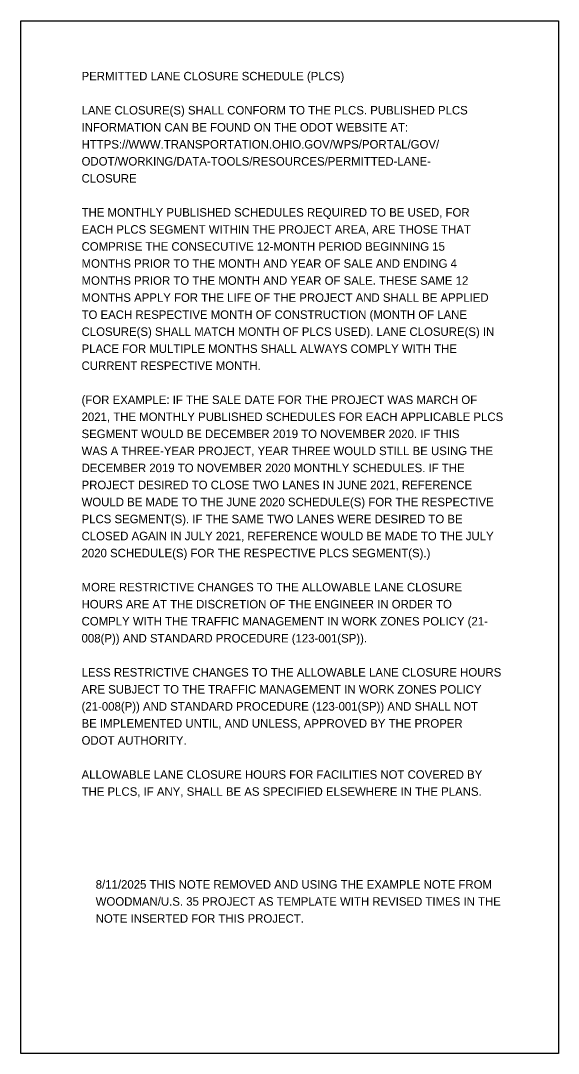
# Model space of a CAD drawing. Extents: x -25.5 to 52.6, y -2.3 to 22.
# Drawn here: x 43.74 to 52.58, y -2.27 to 14.7 of the extents above; entities that cross this region are included whole.
import ezdxf

# ---------------------------------------------------------------- set-up
doc = ezdxf.new("R2010")
doc.units = 0
doc.layers.add('SH_Text', color=7, linetype='Continuous')

msp = doc.modelspace()

# ---------------------------------------------------------------- linework, layer by layer
at = {"layer": 'SH_Text'}
msp.add_lwpolyline([(43.74, 14.702), (52.576, 14.702), (52.576, -2.274), (43.74, -2.274)], close=True, dxfattribs=at)

# ---------------------------------------------------------------- texts
for s, p in [('PERMITTED LANE CLOSURE SCHEDULE (PLCS)', (44.741, 13.72)), ('LANE CLOSURE(S) SHALL CONFORM TO THE PLCS. PUBLISHED PLCS ', (44.741, 13.16)), ('INFORMATION CAN BE FOUND ON THE ODOT WEBSITE AT: ', (44.741, 12.88)), ('HTTPS://WWW.TRANSPORTATION.OHIO.GOV/WPS/PORTAL/GOV/', (44.741, 12.6)), ('ODOT/WORKING/DATA-TOOLS/RESOURCES/PERMITTED-LANE-', (44.741, 12.32)), ('CLOSURE', (44.741, 12.04)), ('THE MONTHLY PUBLISHED SCHEDULES REQUIRED TO BE USED, FOR ', (44.741, 11.48)), ('EACH PLCS SEGMENT WITHIN THE PROJECT AREA, ARE THOSE THAT ', (44.741, 11.2)), ('COMPRISE THE CONSECUTIVE 12-MONTH PERIOD BEGINNING 15 ', (44.741, 10.92)), ('MONTHS PRIOR TO THE MONTH AND YEAR OF SALE AND ENDING 4 ', (44.741, 10.64)), ('MONTHS PRIOR TO THE MONTH AND YEAR OF SALE. THESE SAME 12 ', (44.741, 10.36)), ('MONTHS APPLY FOR THE LIFE OF THE PROJECT AND SHALL BE APPLIED ', (44.741, 10.08)), ('TO EACH RESPECTIVE MONTH OF CONSTRUCTION (MONTH OF LANE ', (44.741, 9.8)), ('CLOSURE(S) SHALL MATCH MONTH OF PLCS USED). LANE CLOSURE(S) IN ', (44.741, 9.52)), ('PLACE FOR MULTIPLE MONTHS SHALL ALWAYS COMPLY WITH THE ', (44.741, 9.24)), ('CURRENT RESPECTIVE MONTH. ', (44.741, 8.96)), ('(FOR EXAMPLE: IF THE SALE DATE FOR THE PROJECT WAS MARCH OF ', (44.741, 8.4)), ('2021, THE MONTHLY PUBLISHED SCHEDULES FOR EACH APPLICABLE PLCS ', (44.741, 8.12)), ('SEGMENT WOULD BE DECEMBER 2019 TO NOVEMBER 2020. IF THIS ', (44.741, 7.84)), ('WAS A THREE-YEAR PROJECT, YEAR THREE WOULD STILL BE USING THE ', (44.741, 7.56)), ('DECEMBER 2019 TO NOVEMBER 2020 MONTHLY SCHEDULES. IF THE ', (44.741, 7.28)), ('PROJECT DESIRED TO CLOSE TWO LANES IN JUNE 2021, REFERENCE ', (44.741, 7)), ('WOULD BE MADE TO THE JUNE 2020 SCHEDULE(S) FOR THE RESPECTIVE ', (44.741, 6.72)), ('PLCS SEGMENT(S). IF THE SAME TWO LANES WERE DESIRED TO BE ', (44.741, 6.44)), ('CLOSED AGAIN IN JULY 2021, REFERENCE WOULD BE MADE TO THE JULY ', (44.741, 6.16)), ('2020 SCHEDULE(S) FOR THE RESPECTIVE PLCS SEGMENT(S).)', (44.741, 5.88)), ('MORE RESTRICTIVE CHANGES TO THE ALLOWABLE LANE CLOSURE ', (44.741, 5.32)), ('HOURS ARE AT THE DISCRETION OF THE ENGINEER IN ORDER TO ', (44.741, 5.04)), ('COMPLY WITH THE TRAFFIC MANAGEMENT IN WORK ZONES POLICY (21-', (44.741, 4.76)), ('008(P)) AND STANDARD PROCEDURE (123-001(SP)). ', (44.741, 4.48)), ('LESS RESTRICTIVE CHANGES TO THE ALLOWABLE LANE CLOSURE HOURS ', (44.741, 3.92)), ('ARE SUBJECT TO THE TRAFFIC MANAGEMENT IN WORK ZONES POLICY ', (44.741, 3.64)), ('(21-008(P)) AND STANDARD PROCEDURE (123-001(SP)) AND SHALL NOT ', (44.741, 3.36)), ('BE IMPLEMENTED UNTIL, AND UNLESS, APPROVED BY THE PROPER ', (44.741, 3.08)), ('ODOT AUTHORITY.', (44.741, 2.8)), ('ALLOWABLE LANE CLOSURE HOURS FOR FACILITIES NOT COVERED BY ', (44.741, 2.24)), ('THE PLCS, IF ANY, SHALL BE AS SPECIFIED ELSEWHERE IN THE PLANS.', (44.741, 1.96)), ('8/11/2025 THIS NOTE REMOVED AND USING THE EXAMPLE NOTE FROM ', (44.973, 0.433)), ('WOODMAN/U.S. 35 PROJECT AS TEMPLATE WITH REVISED TIMES IN THE ', (44.973, 0.153)), ('NOTE INSERTED FOR THIS PROJECT.', (44.973, -0.127))]:
    msp.add_text(s, height=0.14, dxfattribs=at).set_placement(p)

doc.saveas('drawing.dxf')
